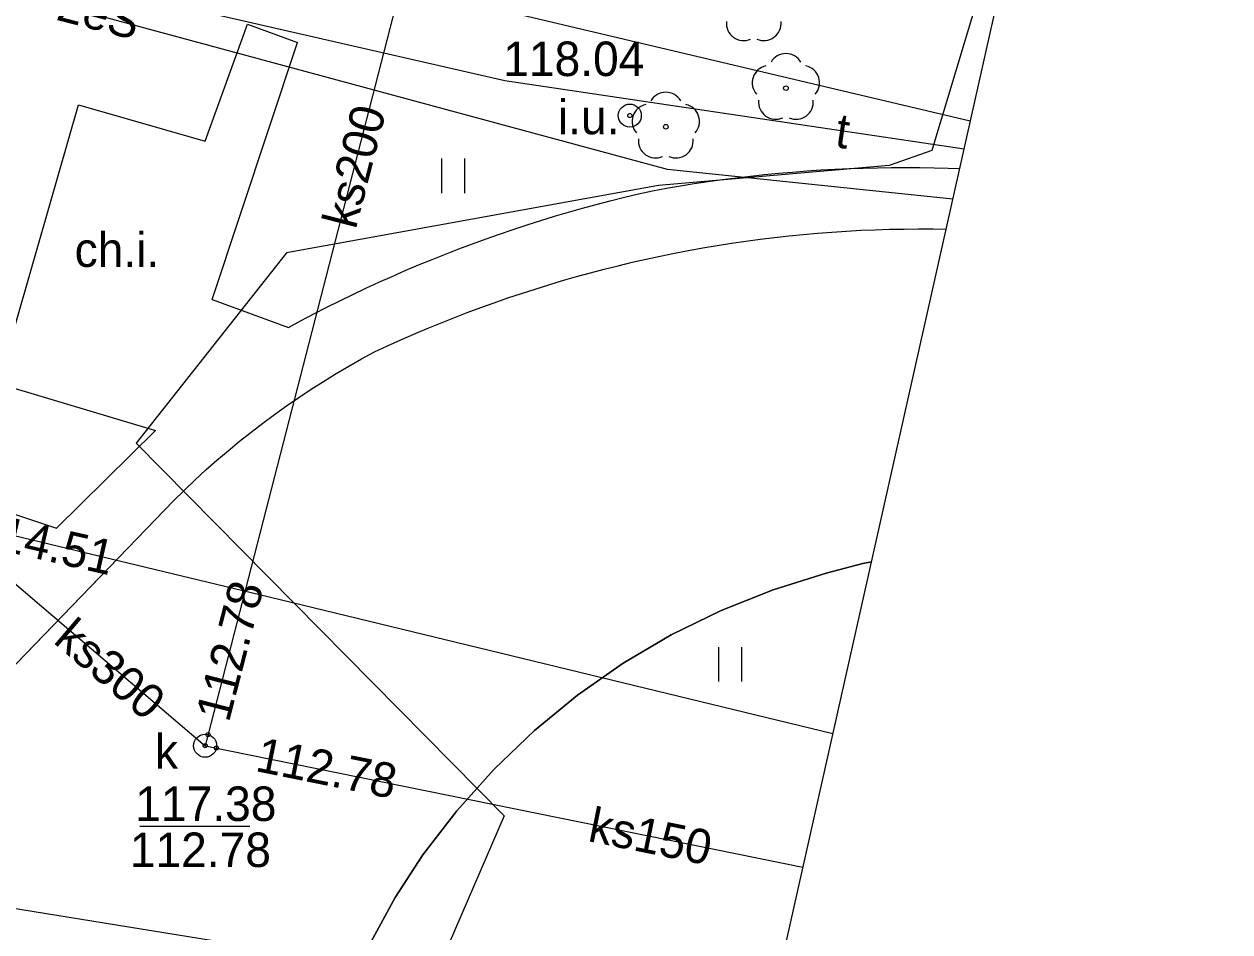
# Model space of a CAD drawing. Extents: x 6424617 to 6425697, y 5665845 to 5667190.
# Drawn here: x 6425421.67 to 6425447.87, y 5666329.12 to 5666348.84 of the extents above; entities that cross this region are included whole.
import ezdxf

# ---------------------------------------------------------------- set-up
doc = ezdxf.new("R2010")
doc.units = 0
for name, color, linetype in [('Warstwa 10', 7, 'Continuous'), ('Warstwa 11', 7, 'Continuous'), ('Warstwa 12', 7, 'Continuous'), ('Warstwa 13', 7, 'Continuous'), ('Warstwa 14', 7, 'Continuous'), ('Warstwa 15', 7, 'Continuous'), ('Warstwa 24', 7, 'Continuous'), ('Warstwa 4', 7, 'Continuous'), ('Warstwa 5', 7, 'Continuous'), ('Warstwa 6', 7, 'Continuous'), ('Warstwa 63', 7, 'Continuous'), ('Warstwa 8', 7, 'Continuous'), ('Warstwa 9', 7, 'Continuous')]:
    doc.layers.add(name, color=color, linetype=linetype)

msp = doc.modelspace()

# ---------------------------------------------------------------- linework, layer by layer
at = {"layer": 'Warstwa 10'}
msp.add_lwpolyline([(6425441.845, 5666345.034), (6425435.644, 5666345.684), (6425416.754, 5666350.792), (6425414.426, 5666349.31), (6425409.689, 5666350.497), (6425397.042, 5666354.07), (6425390.053, 5666355.924), (6425382.597, 5666357.904), (6425376.603, 5666359.336), (6425374.869, 5666359.807), (6425368.783, 5666361.001), (6425351.183, 5666364.453), (6425348.415, 5666364.948)], dxfattribs=at)
at = {"layer": 'Warstwa 11'}
for centre, radius in [((6425438.22, 5666347.45), 0.05), ((6425435.61, 5666346.61), 0.05), ((6425425.6, 5666333.16), 0.25)]:
    msp.add_circle(centre, radius, dxfattribs=at)
for centre, start, end in [((6425437.3, 5666348.857), 174.1471, 293.8529), ((6425437.74, 5666348.857), 246.1471, 5.8529), ((6425438.22, 5666347.825), 30.1471, 149.8529), ((6425437.863, 5666347.566), 102.1471, 221.8529), ((6425438.577, 5666347.566), 318.1471, 77.8529), ((6425435.61, 5666346.985), 30.1471, 149.8529), ((6425435.253, 5666346.726), 102.1471, 221.8529), ((6425435.967, 5666346.726), 318.1471, 77.8529), ((6425438, 5666347.147), 174.1471, 293.8529), ((6425438.44, 5666347.147), 246.1471, 5.8529), ((6425435.39, 5666346.307), 174.1471, 293.8529), ((6425435.83, 5666346.307), 246.1471, 5.8529)]:
    msp.add_arc(centre, 0.375, start, end, dxfattribs=at)
at = {"layer": 'Warstwa 12'}
for points in [[(6425439.24, 5666333.418), (6425426.991, 5666336.388), (6425420.09, 5666338.051), (6425419.57, 5666338.3), (6425418.724, 5666338.388), (6425410.008, 5666340.443), (6425409.32, 5666340.611), (6425409.518, 5666341.279), (6425413.167, 5666353.556), (6425413.365, 5666354.223), (6425412.738, 5666354.531), (6425402.856, 5666359.381), (6425386.87, 5666366.77), (6425385.858, 5666367.253), (6425385.32, 5666367.51), (6425376.142, 5666372.493), (6425375.647, 5666372.869), (6425375.505, 5666373.611), (6425375.267, 5666374.564), (6425373.736, 5666374.755)], [(6425431.352, 5666354.657), (6425430.991, 5666354.097), (6425425.6, 5666333.16)], [(6425415.331, 5666353.099), (6425442.226, 5666346.736)], [(6425442.733, 5666353.01), (6425443.055, 5666352.564), (6425442.431, 5666349.563), (6425441.389, 5666346.095), (6425440.465, 5666345.766), (6425435.449, 5666345.337), (6425427.371, 5666343.874), (6425424.101, 5666339.733), (6425432.094, 5666331.636), (6425430.9, 5666328.87), (6425429.388, 5666323.698), (6425429.751, 5666318.164), (6425432.969, 5666313.154)], [(6425407.427, 5666334.745), (6425408.56, 5666335.13), (6425411.806, 5666343.538), (6425416.324, 5666351.232), (6425432.111, 5666347.615), (6425442.091, 5666346.131)], [(6425372.086, 5666347.268), (6425373.194, 5666346.946), (6425381.905, 5666344.561), (6425389.18, 5666342.374), (6425390.275, 5666342.01), (6425389.074, 5666338.625), (6425388.098, 5666335.616), (6425410.349, 5666331.428), (6425437.797, 5666326.979)], [(6425419.57, 5666338.3), (6425425.6, 5666333.16)], [(6425425.6, 5666333.16), (6425438.591, 5666330.522)]]:
    msp.add_lwpolyline(points, dxfattribs=at)
at = {"layer": 'Warstwa 14'}
msp.add_line((6425426.568, 5666331.405), (6425424.182, 5666331.405), dxfattribs=at)
for centre in [(6425434.828, 5666346.854), (6425425.662, 5666333.402), (6425425.6, 5666333.16), (6425425.845, 5666333.11)]:
    msp.add_circle(centre, 0.045, dxfattribs=at)
at = {"layer": 'Warstwa 24'}
msp.add_circle((6425434.828, 5666346.854), 0.25, dxfattribs=at)
at = {"layer": 'Warstwa 4'}
msp.add_circle((6425425.6, 5666333.16), 0.25, dxfattribs=at)
at = {"layer": 'Warstwa 5'}
for p, q in [((6425425.6, 5666346.3), (6425426.52, 5666348.84)), ((6425426.52, 5666348.84), (6425427.61, 5666348.44)), ((6425425.75, 5666342.86), (6425427.61, 5666348.44)), ((6425421.1, 5666341.03), (6425422.85, 5666347.09)), ((6425422.85, 5666347.09), (6425425.6, 5666346.3)), ((6425430.74, 5666345.169), (6425430.74, 5666345.919)), ((6425431.24, 5666345.169), (6425431.24, 5666345.919)), ((6425438.06, 5666345.6), (6425438.366, 5666345.627)), ((6425438.366, 5666345.627), (6425438.673, 5666345.65)), ((6425438.673, 5666345.65), (6425438.979, 5666345.671)), ((6425438.979, 5666345.671), (6425439.286, 5666345.688)), ((6425439.286, 5666345.688), (6425439.594, 5666345.702)), ((6425439.594, 5666345.702), (6425439.901, 5666345.713)), ((6425439.901, 5666345.713), (6425440.208, 5666345.72)), ((6425440.208, 5666345.72), (6425440.516, 5666345.725)), ((6425440.516, 5666345.725), (6425440.823, 5666345.726)), ((6425440.823, 5666345.726), (6425441.131, 5666345.724)), ((6425441.131, 5666345.724), (6425441.438, 5666345.719)), ((6425441.438, 5666345.719), (6425441.745, 5666345.711)), ((6425441.745, 5666345.711), (6425441.995, 5666345.702)), ((6425435.926, 5666345.326), (6425436.229, 5666345.375)), ((6425436.229, 5666345.375), (6425436.533, 5666345.42)), ((6425436.533, 5666345.42), (6425436.838, 5666345.462)), ((6425436.838, 5666345.462), (6425437.143, 5666345.502)), ((6425437.143, 5666345.502), (6425437.448, 5666345.538)), ((6425437.448, 5666345.538), (6425437.754, 5666345.571)), ((6425437.754, 5666345.571), (6425438.06, 5666345.6)), ((6425434.709, 5666345.077), (6425435.014, 5666345.15)), ((6425435.014, 5666345.15), (6425435.32, 5666345.22)), ((6425435.32, 5666345.22), (6425435.623, 5666345.275)), ((6425435.623, 5666345.275), (6425435.926, 5666345.326)), ((6425433.495, 5666344.754), (6425433.797, 5666344.839)), ((6425433.797, 5666344.839), (6425434.1, 5666344.922)), ((6425434.1, 5666344.922), (6425434.404, 5666345.001)), ((6425434.404, 5666345.001), (6425434.709, 5666345.077)), ((6425432.594, 5666344.478), (6425432.894, 5666344.573)), ((6425432.894, 5666344.573), (6425433.194, 5666344.665)), ((6425433.194, 5666344.665), (6425433.495, 5666344.754)), ((6425431.999, 5666344.279), (6425432.296, 5666344.38)), ((6425432.296, 5666344.38), (6425432.594, 5666344.478)), ((6425431.114, 5666343.957), (6425431.408, 5666344.068)), ((6425431.408, 5666344.068), (6425431.703, 5666344.175)), ((6425431.703, 5666344.175), (6425431.999, 5666344.279)), ((6425430.53, 5666343.727), (6425430.821, 5666343.844)), ((6425430.821, 5666343.844), (6425431.114, 5666343.957)), ((6425429.95, 5666343.485), (6425430.239, 5666343.608)), ((6425430.239, 5666343.608), (6425430.53, 5666343.727)), ((6425429.376, 5666343.231), (6425429.662, 5666343.36)), ((6425429.662, 5666343.36), (6425429.95, 5666343.485)), ((6425428.807, 5666342.966), (6425429.091, 5666343.1)), ((6425429.091, 5666343.1), (6425429.376, 5666343.231)), ((6425425.75, 5666342.86), (6425427.41, 5666342.25)), ((6425428.244, 5666342.688), (6425428.525, 5666342.828)), ((6425428.525, 5666342.828), (6425428.807, 5666342.966)), ((6425427.686, 5666342.399), (6425427.964, 5666342.545)), ((6425427.964, 5666342.545), (6425428.244, 5666342.688)), ((6425427.41, 5666342.25), (6425427.686, 5666342.399)), ((6425421.1, 5666341.03), (6425424.52, 5666340.01)), ((6425422.37, 5666337.89), (6425424.52, 5666340.01)), ((6425417.66, 5666339.46), (6425422.37, 5666337.89)), ((6425439.098, 5666336.912), (6425439.888, 5666337.123)), ((6425439.888, 5666337.123), (6425440.079, 5666337.159)), ((6425437.942, 5666336.551), (6425439.098, 5666336.912)), ((6425436.816, 5666336.102), (6425437.942, 5666336.551)), ((6425435.728, 5666335.568), (6425436.816, 5666336.102)), ((6425434.685, 5666334.952), (6425435.728, 5666335.568)), ((6425436.763, 5666334.555), (6425436.763, 5666335.305)), ((6425437.263, 5666334.555), (6425437.263, 5666335.305)), ((6425433.691, 5666334.258), (6425434.685, 5666334.952)), ((6425432.754, 5666333.49), (6425433.691, 5666334.258)), ((6425431.879, 5666332.652), (6425432.754, 5666333.49)), ((6425431.07, 5666331.749), (6425431.879, 5666332.652)), ((6425430.333, 5666330.787), (6425431.07, 5666331.749)), ((6425429.729, 5666329.861), (6425430.333, 5666330.787)), ((6425429.2, 5666328.891), (6425429.729, 5666329.861))]:
    msp.add_line(p, q, dxfattribs=at)
at = {"layer": 'Warstwa 6'}
for points in [[(6425416.08, 5666329.34), (6425424.92, 5666338.49), (6425425.148, 5666338.715), (6425425.381, 5666338.935), (6425425.617, 5666339.152), (6425425.857, 5666339.364), (6425426.1, 5666339.572), (6425426.347, 5666339.776), (6425426.598, 5666339.975), (6425426.852, 5666340.17), (6425427.11, 5666340.361), (6425427.37, 5666340.547), (6425427.634, 5666340.729), (6425427.901, 5666340.906), (6425428.171, 5666341.078), (6425428.444, 5666341.246), (6425428.72, 5666341.409), (6425428.999, 5666341.567), (6425429.28, 5666341.72), (6425429.564, 5666341.851), (6425429.849, 5666341.979), (6425430.135, 5666342.105), (6425430.423, 5666342.226), (6425430.712, 5666342.345), (6425431.003, 5666342.461), (6425431.294, 5666342.573), (6425431.587, 5666342.682), (6425431.881, 5666342.788), (6425432.177, 5666342.89), (6425432.473, 5666342.989), (6425432.77, 5666343.085), (6425433.069, 5666343.178), (6425433.368, 5666343.267), (6425433.669, 5666343.354), (6425433.97, 5666343.436), (6425434.273, 5666343.516), (6425434.576, 5666343.592), (6425434.88, 5666343.665), (6425435.184, 5666343.734), (6425435.49, 5666343.8), (6425435.798, 5666343.863), (6425436.106, 5666343.923), (6425436.415, 5666343.979), (6425436.725, 5666344.032), (6425437.035, 5666344.081), (6425437.346, 5666344.126), (6425437.657, 5666344.168), (6425437.969, 5666344.206), (6425438.281, 5666344.241), (6425438.593, 5666344.272), (6425438.906, 5666344.299), (6425439.219, 5666344.323), (6425439.533, 5666344.343), (6425439.846, 5666344.36), (6425440.16, 5666344.373), (6425440.474, 5666344.382), (6425440.788, 5666344.388), (6425441.102, 5666344.39), (6425441.416, 5666344.389), (6425441.699, 5666344.384)], [(6425440.079, 5666337.159), (6425439.888, 5666337.123), (6425439.098, 5666336.912), (6425437.942, 5666336.551), (6425436.816, 5666336.102), (6425435.728, 5666335.568), (6425434.685, 5666334.952), (6425433.691, 5666334.258), (6425432.754, 5666333.49), (6425431.879, 5666332.652), (6425431.07, 5666331.749), (6425430.333, 5666330.787), (6425429.729, 5666329.861), (6425429.2, 5666328.891)]]:
    msp.add_lwpolyline(points, dxfattribs=at)
at = {"layer": 'Warstwa 63'}
msp.add_lwpolyline([(6425341.164, 5665895.978), (6425588.9, 5667000.928), (6424898.307, 5667155.763), (6424650.57, 5666050.814)], close=True, dxfattribs=at)
at = {"layer": 'Warstwa 8'}
for p, q in [((6425438.906, 5666344.299), (6425439.219, 5666344.323)), ((6425439.219, 5666344.323), (6425439.533, 5666344.343)), ((6425439.533, 5666344.343), (6425439.846, 5666344.36)), ((6425439.846, 5666344.36), (6425440.16, 5666344.373)), ((6425440.16, 5666344.373), (6425440.474, 5666344.382)), ((6425440.474, 5666344.382), (6425440.788, 5666344.388)), ((6425440.788, 5666344.388), (6425441.102, 5666344.39)), ((6425441.102, 5666344.39), (6425441.416, 5666344.389)), ((6425441.416, 5666344.389), (6425441.699, 5666344.384)), ((6425436.725, 5666344.032), (6425437.035, 5666344.081)), ((6425437.035, 5666344.081), (6425437.346, 5666344.126)), ((6425437.346, 5666344.126), (6425437.657, 5666344.168)), ((6425437.657, 5666344.168), (6425437.969, 5666344.206)), ((6425437.969, 5666344.206), (6425438.281, 5666344.241)), ((6425438.281, 5666344.241), (6425438.593, 5666344.272)), ((6425438.593, 5666344.272), (6425438.906, 5666344.299)), ((6425435.184, 5666343.734), (6425435.49, 5666343.8)), ((6425435.49, 5666343.8), (6425435.798, 5666343.863)), ((6425435.798, 5666343.863), (6425436.106, 5666343.923)), ((6425436.106, 5666343.923), (6425436.415, 5666343.979)), ((6425436.415, 5666343.979), (6425436.725, 5666344.032)), ((6425434.273, 5666343.516), (6425434.576, 5666343.592)), ((6425434.576, 5666343.592), (6425434.88, 5666343.665)), ((6425434.88, 5666343.665), (6425435.184, 5666343.734)), ((6425433.069, 5666343.178), (6425433.368, 5666343.267)), ((6425433.368, 5666343.267), (6425433.669, 5666343.354)), ((6425433.669, 5666343.354), (6425433.97, 5666343.436)), ((6425433.97, 5666343.436), (6425434.273, 5666343.516)), ((6425432.473, 5666342.989), (6425432.77, 5666343.085)), ((6425432.77, 5666343.085), (6425433.069, 5666343.178)), ((6425431.587, 5666342.682), (6425431.881, 5666342.788)), ((6425431.881, 5666342.788), (6425432.177, 5666342.89)), ((6425432.177, 5666342.89), (6425432.473, 5666342.989)), ((6425431.003, 5666342.461), (6425431.294, 5666342.573)), ((6425431.294, 5666342.573), (6425431.587, 5666342.682)), ((6425430.135, 5666342.105), (6425430.423, 5666342.226)), ((6425430.423, 5666342.226), (6425430.712, 5666342.345)), ((6425430.712, 5666342.345), (6425431.003, 5666342.461)), ((6425429.564, 5666341.851), (6425429.849, 5666341.979)), ((6425429.849, 5666341.979), (6425430.135, 5666342.105)), ((6425428.999, 5666341.567), (6425429.28, 5666341.72)), ((6425429.28, 5666341.72), (6425429.564, 5666341.851)), ((6425428.72, 5666341.409), (6425428.999, 5666341.567)), ((6425428.171, 5666341.078), (6425428.444, 5666341.246)), ((6425428.444, 5666341.246), (6425428.72, 5666341.409)), ((6425427.634, 5666340.729), (6425427.901, 5666340.906)), ((6425427.901, 5666340.906), (6425428.171, 5666341.078)), ((6425427.37, 5666340.547), (6425427.634, 5666340.729)), ((6425427.11, 5666340.361), (6425427.37, 5666340.547)), ((6425426.598, 5666339.975), (6425426.852, 5666340.17)), ((6425426.852, 5666340.17), (6425427.11, 5666340.361)), ((6425426.347, 5666339.776), (6425426.598, 5666339.975)), ((6425426.1, 5666339.572), (6425426.347, 5666339.776)), ((6425425.617, 5666339.152), (6425425.857, 5666339.364)), ((6425425.857, 5666339.364), (6425426.1, 5666339.572)), ((6425425.381, 5666338.935), (6425425.617, 5666339.152)), ((6425425.148, 5666338.715), (6425425.381, 5666338.935)), ((6425424.92, 5666338.49), (6425425.148, 5666338.715)), ((6425416.08, 5666329.34), (6425424.92, 5666338.49)), ((6425439.098, 5666336.912), (6425439.888, 5666337.123)), ((6425439.888, 5666337.123), (6425440.079, 5666337.159)), ((6425437.942, 5666336.551), (6425439.098, 5666336.912)), ((6425436.816, 5666336.102), (6425437.942, 5666336.551)), ((6425435.728, 5666335.568), (6425436.816, 5666336.102)), ((6425434.685, 5666334.952), (6425435.728, 5666335.568)), ((6425433.691, 5666334.258), (6425434.685, 5666334.952)), ((6425432.754, 5666333.49), (6425433.691, 5666334.258)), ((6425431.879, 5666332.652), (6425432.754, 5666333.49)), ((6425431.07, 5666331.749), (6425431.879, 5666332.652)), ((6425430.333, 5666330.787), (6425431.07, 5666331.749)), ((6425429.729, 5666329.861), (6425430.333, 5666330.787)), ((6425429.2, 5666328.891), (6425429.729, 5666329.861))]:
    msp.add_line(p, q, dxfattribs=at)
at = {"layer": 'Warstwa 9'}
for p, q in [((6425425.6, 5666346.3), (6425426.52, 5666348.84)), ((6425426.52, 5666348.84), (6425427.61, 5666348.44)), ((6425425.75, 5666342.86), (6425427.61, 5666348.44)), ((6425421.1, 5666341.03), (6425422.85, 5666347.09)), ((6425422.85, 5666347.09), (6425425.6, 5666346.3)), ((6425438.06, 5666345.6), (6425438.366, 5666345.627)), ((6425438.366, 5666345.627), (6425438.673, 5666345.65)), ((6425438.673, 5666345.65), (6425438.979, 5666345.671)), ((6425438.979, 5666345.671), (6425439.286, 5666345.688)), ((6425439.286, 5666345.688), (6425439.594, 5666345.702)), ((6425439.594, 5666345.702), (6425439.901, 5666345.713)), ((6425439.901, 5666345.713), (6425440.208, 5666345.72)), ((6425440.208, 5666345.72), (6425440.516, 5666345.725)), ((6425440.516, 5666345.725), (6425440.823, 5666345.726)), ((6425440.823, 5666345.726), (6425441.131, 5666345.724)), ((6425441.131, 5666345.724), (6425441.438, 5666345.719)), ((6425441.438, 5666345.719), (6425441.745, 5666345.711)), ((6425441.745, 5666345.711), (6425441.995, 5666345.702)), ((6425435.926, 5666345.326), (6425436.229, 5666345.375)), ((6425436.229, 5666345.375), (6425436.533, 5666345.42)), ((6425436.533, 5666345.42), (6425436.838, 5666345.462)), ((6425436.838, 5666345.462), (6425437.143, 5666345.502)), ((6425437.143, 5666345.502), (6425437.448, 5666345.538)), ((6425437.448, 5666345.538), (6425437.754, 5666345.571)), ((6425437.754, 5666345.571), (6425438.06, 5666345.6)), ((6425434.709, 5666345.077), (6425435.014, 5666345.15)), ((6425435.014, 5666345.15), (6425435.32, 5666345.22)), ((6425435.32, 5666345.22), (6425435.623, 5666345.275)), ((6425435.623, 5666345.275), (6425435.926, 5666345.326)), ((6425433.495, 5666344.754), (6425433.797, 5666344.839)), ((6425433.797, 5666344.839), (6425434.1, 5666344.922)), ((6425434.1, 5666344.922), (6425434.404, 5666345.001)), ((6425434.404, 5666345.001), (6425434.709, 5666345.077)), ((6425432.594, 5666344.478), (6425432.894, 5666344.573)), ((6425432.894, 5666344.573), (6425433.194, 5666344.665)), ((6425433.194, 5666344.665), (6425433.495, 5666344.754)), ((6425431.999, 5666344.279), (6425432.296, 5666344.38)), ((6425432.296, 5666344.38), (6425432.594, 5666344.478)), ((6425438.906, 5666344.299), (6425439.219, 5666344.323)), ((6425439.219, 5666344.323), (6425439.533, 5666344.343)), ((6425439.533, 5666344.343), (6425439.846, 5666344.36)), ((6425439.846, 5666344.36), (6425440.16, 5666344.373)), ((6425440.16, 5666344.373), (6425440.474, 5666344.382)), ((6425440.474, 5666344.382), (6425440.788, 5666344.388)), ((6425440.788, 5666344.388), (6425441.102, 5666344.39)), ((6425441.102, 5666344.39), (6425441.416, 5666344.389)), ((6425441.416, 5666344.389), (6425441.699, 5666344.384)), ((6425431.114, 5666343.957), (6425431.408, 5666344.068)), ((6425431.408, 5666344.068), (6425431.703, 5666344.175)), ((6425431.703, 5666344.175), (6425431.999, 5666344.279)), ((6425436.725, 5666344.032), (6425437.035, 5666344.081)), ((6425437.035, 5666344.081), (6425437.346, 5666344.126)), ((6425437.346, 5666344.126), (6425437.657, 5666344.168)), ((6425437.657, 5666344.168), (6425437.969, 5666344.206)), ((6425437.969, 5666344.206), (6425438.281, 5666344.241)), ((6425438.281, 5666344.241), (6425438.593, 5666344.272)), ((6425438.593, 5666344.272), (6425438.906, 5666344.299)), ((6425430.53, 5666343.727), (6425430.821, 5666343.844)), ((6425430.821, 5666343.844), (6425431.114, 5666343.957)), ((6425435.184, 5666343.734), (6425435.49, 5666343.8)), ((6425435.49, 5666343.8), (6425435.798, 5666343.863)), ((6425435.798, 5666343.863), (6425436.106, 5666343.923)), ((6425436.106, 5666343.923), (6425436.415, 5666343.979)), ((6425436.415, 5666343.979), (6425436.725, 5666344.032)), ((6425429.95, 5666343.485), (6425430.239, 5666343.608)), ((6425430.239, 5666343.608), (6425430.53, 5666343.727)), ((6425434.273, 5666343.516), (6425434.576, 5666343.592)), ((6425434.576, 5666343.592), (6425434.88, 5666343.665)), ((6425434.88, 5666343.665), (6425435.184, 5666343.734)), ((6425429.376, 5666343.231), (6425429.662, 5666343.36)), ((6425429.662, 5666343.36), (6425429.95, 5666343.485)), ((6425433.069, 5666343.178), (6425433.368, 5666343.267)), ((6425433.368, 5666343.267), (6425433.669, 5666343.354)), ((6425433.669, 5666343.354), (6425433.97, 5666343.436)), ((6425433.97, 5666343.436), (6425434.273, 5666343.516)), ((6425428.807, 5666342.966), (6425429.091, 5666343.1)), ((6425429.091, 5666343.1), (6425429.376, 5666343.231)), ((6425432.473, 5666342.989), (6425432.77, 5666343.085)), ((6425432.77, 5666343.085), (6425433.069, 5666343.178)), ((6425425.75, 5666342.86), (6425427.41, 5666342.25)), ((6425428.244, 5666342.688), (6425428.525, 5666342.828)), ((6425428.525, 5666342.828), (6425428.807, 5666342.966)), ((6425431.587, 5666342.682), (6425431.881, 5666342.788)), ((6425431.881, 5666342.788), (6425432.177, 5666342.89)), ((6425432.177, 5666342.89), (6425432.473, 5666342.989)), ((6425427.686, 5666342.399), (6425427.964, 5666342.545)), ((6425427.964, 5666342.545), (6425428.244, 5666342.688)), ((6425431.003, 5666342.461), (6425431.294, 5666342.573)), ((6425431.294, 5666342.573), (6425431.587, 5666342.682)), ((6425427.41, 5666342.25), (6425427.686, 5666342.399)), ((6425430.135, 5666342.105), (6425430.423, 5666342.226)), ((6425430.423, 5666342.226), (6425430.712, 5666342.345)), ((6425430.712, 5666342.345), (6425431.003, 5666342.461)), ((6425429.564, 5666341.851), (6425429.849, 5666341.979)), ((6425429.849, 5666341.979), (6425430.135, 5666342.105)), ((6425428.999, 5666341.567), (6425429.28, 5666341.72)), ((6425429.28, 5666341.72), (6425429.564, 5666341.851)), ((6425428.72, 5666341.409), (6425428.999, 5666341.567)), ((6425428.171, 5666341.078), (6425428.444, 5666341.246)), ((6425428.444, 5666341.246), (6425428.72, 5666341.409)), ((6425421.1, 5666341.03), (6425424.52, 5666340.01)), ((6425427.634, 5666340.729), (6425427.901, 5666340.906)), ((6425427.901, 5666340.906), (6425428.171, 5666341.078)), ((6425427.37, 5666340.547), (6425427.634, 5666340.729)), ((6425427.11, 5666340.361), (6425427.37, 5666340.547)), ((6425426.598, 5666339.975), (6425426.852, 5666340.17)), ((6425426.852, 5666340.17), (6425427.11, 5666340.361)), ((6425422.37, 5666337.89), (6425424.52, 5666340.01)), ((6425426.347, 5666339.776), (6425426.598, 5666339.975)), ((6425426.1, 5666339.572), (6425426.347, 5666339.776)), ((6425417.66, 5666339.46), (6425422.37, 5666337.89)), ((6425425.617, 5666339.152), (6425425.857, 5666339.364)), ((6425425.857, 5666339.364), (6425426.1, 5666339.572)), ((6425425.381, 5666338.935), (6425425.617, 5666339.152)), ((6425425.148, 5666338.715), (6425425.381, 5666338.935)), ((6425424.92, 5666338.49), (6425425.148, 5666338.715)), ((6425416.08, 5666329.34), (6425424.92, 5666338.49))]:
    msp.add_line(p, q, dxfattribs=at)

# ---------------------------------------------------------------- texts
at = {"layer": 'Warstwa 11'}
msp.add_text('2eS', height=0.75, rotation=345.5566, dxfattribs=at).set_placement((6425422.339, 5666348.94))
at = {"layer": 'Warstwa 13'}
for s, rotation, p in [('ks200', 75.5617, (6425428.871, 5666344.363)), ('t', 351.544, (6425439.266, 5666346.172)), ('ks300', 319.5558, (6425422.279, 5666335.412)), ('ks150', 348.5245, (6425433.893, 5666331.093))]:
    msp.add_text(s, height=0.75, rotation=rotation, dxfattribs=at).set_placement(p)
at = {"layer": 'Warstwa 14'}
for s, rotation, p in [('114.51', 347.1379, (6425420.527, 5666337.546)), ('112.78', 75.5617, (6425426.114, 5666333.647)), ('112.78', 348.5245, (6425426.666, 5666332.615))]:
    msp.add_text(s, height=0.75, rotation=rotation, dxfattribs=at).set_placement(p)
msp.add_text('112.78', height=0.75, dxfattribs=at).set_placement((6425423.963, 5666330.525))
at = {"layer": 'Warstwa 15'}
for s, p in [('118.04', (6425432.077, 5666347.712)), ('117.38', (6425424.082, 5666331.525))]:
    msp.add_text(s, height=0.75, dxfattribs=at).set_placement(p)
at = {"layer": 'Warstwa 24'}
msp.add_text('i.u.', height=0.75, dxfattribs=at).set_placement((6425433.265, 5666346.449))
at = {"layer": 'Warstwa 5'}
msp.add_text('k', height=0.75, dxfattribs=at).set_placement((6425424.507, 5666332.665))
at = {"layer": 'Warstwa 9'}
msp.add_text('ch.i.', height=0.75, dxfattribs=at).set_placement((6425422.763, 5666343.564))

doc.saveas('drawing.dxf')
